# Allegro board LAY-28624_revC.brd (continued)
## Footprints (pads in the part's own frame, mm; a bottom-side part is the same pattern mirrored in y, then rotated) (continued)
BGA_P080_NAND_63
  round 0.35 smd: A1(-3.6,4.4) A2(-2.8,4.4) A9(2.8,4.4) A10(3.6,4.4) B1(-3.6,3.6) B9(2.8,3.6) B10(3.6,3.6) C3(-2,2.8) C4(-1.2,2.8) C5(-0.4,2.8) C6(0.4,2.8) C7(1.2,2.8) C8(2,2.8) D3(-2,2) D4(-1.2,2) D5(-0.4,2) D6(0.4,2) D7(1.2,2) D8(2,2) E3(-2,1.2) E4(-1.2,1.2) E5(-0.4,1.2) E6(0.4,1.2) E7(1.2,1.2) E8(2,1.2) F3(-2,0.4) F4(-1.2,0.4) F5(-0.4,0.4) F6(0.4,0.4) F7(1.2,0.4) F8(2,0.4) G3(-2,-0.4) G4(-1.2,-0.4) G5(-0.4,-0.4) G6(0.4,-0.4) G7(1.2,-0.4) G8(2,-0.4) H3(-2,-1.2) H4(-1.2,-1.2) H5(-0.4,-1.2) H6(0.4,-1.2) H7(1.2,-1.2) H8(2,-1.2) J3(-2,-2) J4(-1.2,-2) J5(-0.4,-2) J6(0.4,-2) J7(1.2,-2) J8(2,-2) K3(-2,-2.8) K4(-1.2,-2.8) K5(-0.4,-2.8) K6(0.4,-2.8) K7(1.2,-2.8) K8(2,-2.8) L1(-3.6,-3.6) L2(-2.8,-3.6) L9(2.8,-3.6) L10(3.6,-3.6) M1(-3.6,-4.4) M2(-2.8,-4.4) M9(2.8,-4.4) M10(3.6,-4.4)
BGA_P100_256
  round 0.4 smd: A1(-7.5,7.5) A2(-6.5,7.5) A3(-5.5,7.5) A4(-4.5,7.5) A5(-3.5,7.5) A6(-2.5,7.5) A7(-1.5,7.5) A8(-0.5,7.5) A9(0.5,7.5) A10(1.5,7.5) A11(2.5,7.5) A12(3.5,7.5) A13(4.5,7.5) A14(5.5,7.5) A15(6.5,7.5) A16(7.5,7.5) B1(-7.5,6.5) B2(-6.5,6.5) B3(-5.5,6.5) B4(-4.5,6.5) B5(-3.5,6.5) B6(-2.5,6.5) B7(-1.5,6.5) B8(-0.5,6.5) B9(0.5,6.5) B10(1.5,6.5) B11(2.5,6.5) B12(3.5,6.5) B13(4.5,6.5) B14(5.5,6.5) B15(6.5,6.5) B16(7.5,6.5) C1(-7.5,5.5) C2(-6.5,5.5) C3(-5.5,5.5) C4(-4.5,5.5) C5(-3.5,5.5) C6(-2.5,5.5) C7(-1.5,5.5) C8(-0.5,5.5) C9(0.5,5.5) C10(1.5,5.5) C11(2.5,5.5) C12(3.5,5.5) C13(4.5,5.5) C14(5.5,5.5) C15(6.5,5.5) C16(7.5,5.5) D1(-7.5,4.5) D2(-6.5,4.5) D3(-5.5,4.5) D4(-4.5,4.5) D5(-3.5,4.5) D6(-2.5,4.5) D7(-1.5,4.5) D8(-0.5,4.5) D9(0.5,4.5) D10(1.5,4.5) D11(2.5,4.5) D12(3.5,4.5) D13(4.5,4.5) D14(5.5,4.5) D15(6.5,4.5) D16(7.5,4.5) E1(-7.5,3.5) E2(-6.5,3.5) E3(-5.5,3.5) E4(-4.5,3.5) E5(-3.5,3.5) E6(-2.5,3.5) E7(-1.5,3.5) E8(-0.5,3.5) E9(0.5,3.5) E10(1.5,3.5) E11(2.5,3.5) E12(3.5,3.5) E13(4.5,3.5) E14(5.5,3.5) E15(6.5,3.5) E16(7.5,3.5) F1(-7.5,2.5) F2(-6.5,2.5) F3(-5.5,2.5) F4(-4.5,2.5) F5(-3.5,2.5) F6(-2.5,2.5) F7(-1.5,2.5) F8(-0.5,2.5) F9(0.5,2.5) F10(1.5,2.5) F11(2.5,2.5) F12(3.5,2.5) F13(4.5,2.5) F14(5.5,2.5) F15(6.5,2.5) F16(7.5,2.5) G1(-7.5,1.5) G2(-6.5,1.5) G3(-5.5,1.5) G4(-4.5,1.5) G5(-3.5,1.5) G6(-2.5,1.5) G7(-1.5,1.5) G8(-0.5,1.5) G9(0.5,1.5) G10(1.5,1.5) G11(2.5,1.5) G12(3.5,1.5) G13(4.5,1.5) G14(5.5,1.5) G15(6.5,1.5) G16(7.5,1.5) H1(-7.5,0.5) H2(-6.5,0.5) H3(-5.5,0.5) H4(-4.5,0.5) H5(-3.5,0.5) H6(-2.5,0.5) H7(-1.5,0.5) H8(-0.5,0.5) H9(0.5,0.5) H10(1.5,0.5) H11(2.5,0.5) H12(3.5,0.5) H13(4.5,0.5) H14(5.5,0.5) H15(6.5,0.5) H16(7.5,0.5) J1(-7.5,-0.5) J2(-6.5,-0.5) J3(-5.5,-0.5) J4(-4.5,-0.5) J5(-3.5,-0.5) J6(-2.5,-0.5) J7(-1.5,-0.5) J8(-0.5,-0.5) J9(0.5,-0.5) J10(1.5,-0.5) J11(2.5,-0.5) J12(3.5,-0.5) J13(4.5,-0.5) J14(5.5,-0.5) J15(6.5,-0.5) J16(7.5,-0.5) K1(-7.5,-1.5) K2(-6.5,-1.5) K3(-5.5,-1.5) K4(-4.5,-1.5) K5(-3.5,-1.5) K6(-2.5,-1.5) K7(-1.5,-1.5) K8(-0.5,-1.5) K9(0.5,-1.5) K10(1.5,-1.5) K11(2.5,-1.5) K12(3.5,-1.5) K13(4.5,-1.5) K14(5.5,-1.5) K15(6.5,-1.5) K16(7.5,-1.5) L1(-7.5,-2.5) L2(-6.5,-2.5) L3(-5.5,-2.5) L4(-4.5,-2.5) L5(-3.5,-2.5) L6(-2.5,-2.5) L7(-1.5,-2.5) L8(-0.5,-2.5) L9(0.5,-2.5) L10(1.5,-2.5) L11(2.5,-2.5) L12(3.5,-2.5) L13(4.5,-2.5) L14(5.5,-2.5) L15(6.5,-2.5) L16(7.5,-2.5) M1(-7.5,-3.5) M2(-6.5,-3.5) M3(-5.5,-3.5) M4(-4.5,-3.5) M5(-3.5,-3.5) M6(-2.5,-3.5) M7(-1.5,-3.5) M8(-0.5,-3.5) M9(0.5,-3.5) M10(1.5,-3.5) M11(2.5,-3.5) M12(3.5,-3.5) M13(4.5,-3.5) M14(5.5,-3.5) M15(6.5,-3.5) M16(7.5,-3.5) N1(-7.5,-4.5) N2(-6.5,-4.5) N3(-5.5,-4.5) N4(-4.5,-4.5) N5(-3.5,-4.5) N6(-2.5,-4.5) N7(-1.5,-4.5) N8(-0.5,-4.5) N9(0.5,-4.5) N10(1.5,-4.5) N11(2.5,-4.5) N12(3.5,-4.5) N13(4.5,-4.5) N14(5.5,-4.5) N15(6.5,-4.5) N16(7.5,-4.5) P1(-7.5,-5.5) P2(-6.5,-5.5) P3(-5.5,-5.5) P4(-4.5,-5.5) P5(-3.5,-5.5) P6(-2.5,-5.5) P7(-1.5,-5.5) P8(-0.5,-5.5) P9(0.5,-5.5) P10(1.5,-5.5) P11(2.5,-5.5) P12(3.5,-5.5) P13(4.5,-5.5) P14(5.5,-5.5) P15(6.5,-5.5) P16(7.5,-5.5) R1(-7.5,-6.5) R2(-6.5,-6.5) R3(-5.5,-6.5) R4(-4.5,-6.5) R5(-3.5,-6.5) R6(-2.5,-6.5) R7(-1.5,-6.5) R8(-0.5,-6.5) R9(0.5,-6.5) R10(1.5,-6.5) R11(2.5,-6.5) R12(3.5,-6.5) R13(4.5,-6.5) R14(5.5,-6.5) R15(6.5,-6.5) R16(7.5,-6.5) T1(-7.5,-7.5) T2(-6.5,-7.5) T3(-5.5,-7.5) T4(-4.5,-7.5) T5(-3.5,-7.5) T6(-2.5,-7.5) T7(-1.5,-7.5) T8(-0.5,-7.5) T9(0.5,-7.5) T10(1.5,-7.5) T11(2.5,-7.5) T12(3.5,-7.5) T13(4.5,-7.5) T14(5.5,-7.5) T15(6.5,-7.5) T16(7.5,-7.5)
BGA_P100_324
  round 0.4 smd: A1(-8.5,8.5) A2(-7.5,8.5) A3(-6.5,8.5) A4(-5.5,8.5) A5(-4.5,8.5) A6(-3.5,8.5) A7(-2.5,8.5) A8(-1.5,8.5) A9(-0.5,8.5) A10(0.5,8.5) A11(1.5,8.5) A12(2.5,8.5) A13(3.5,8.5) A14(4.5,8.5) A15(5.5,8.5) A16(6.5,8.5) A17(7.5,8.5) A18(8.5,8.5) B1(-8.5,7.5) B2(-7.5,7.5) B3(-6.5,7.5) B4(-5.5,7.5) B5(-4.5,7.5) B6(-3.5,7.5) B7(-2.5,7.5) B8(-1.5,7.5) B9(-0.5,7.5) B10(0.5,7.5) B11(1.5,7.5) B12(2.5,7.5) B13(3.5,7.5) B14(4.5,7.5) B15(5.5,7.5) B16(6.5,7.5) B17(7.5,7.5) B18(8.5,7.5) C1(-8.5,6.5) C2(-7.5,6.5) C3(-6.5,6.5) C4(-5.5,6.5) C5(-4.5,6.5) C6(-3.5,6.5) C7(-2.5,6.5) C8(-1.5,6.5) C9(-0.5,6.5) C10(0.5,6.5) C11(1.5,6.5) C12(2.5,6.5) C13(3.5,6.5) C14(4.5,6.5) C15(5.5,6.5) C16(6.5,6.5) C17(7.5,6.5) C18(8.5,6.5) D1(-8.5,5.5) D2(-7.5,5.5) D3(-6.5,5.5) D4(-5.5,5.5) D5(-4.5,5.5) D6(-3.5,5.5) D7(-2.5,5.5) D8(-1.5,5.5) D9(-0.5,5.5) D10(0.5,5.5) D11(1.5,5.5) D12(2.5,5.5) D13(3.5,5.5) D14(4.5,5.5) D15(5.5,5.5) D16(6.5,5.5) D17(7.5,5.5) D18(8.5,5.5) E1(-8.5,4.5) E2(-7.5,4.5) E3(-6.5,4.5) E4(-5.5,4.5) E5(-4.5,4.5) E6(-3.5,4.5) E7(-2.5,4.5) E8(-1.5,4.5) E9(-0.5,4.5) E10(0.5,4.5) E11(1.5,4.5) E12(2.5,4.5) E13(3.5,4.5) E14(4.5,4.5) E15(5.5,4.5) E16(6.5,4.5) E17(7.5,4.5) E18(8.5,4.5) F1(-8.5,3.5) F2(-7.5,3.5) F3(-6.5,3.5) F4(-5.5,3.5) F5(-4.5,3.5) F6(-3.5,3.5) F7(-2.5,3.5) F8(-1.5,3.5) F9(-0.5,3.5) F10(0.5,3.5) F11(1.5,3.5) F12(2.5,3.5) F13(3.5,3.5) F14(4.5,3.5) F15(5.5,3.5) F16(6.5,3.5) F17(7.5,3.5) F18(8.5,3.5) G1(-8.5,2.5) G2(-7.5,2.5) G3(-6.5,2.5) G4(-5.5,2.5) G5(-4.5,2.5) G6(-3.5,2.5) G7(-2.5,2.5) G8(-1.5,2.5) G9(-0.5,2.5) G10(0.5,2.5) G11(1.5,2.5) G12(2.5,2.5) G13(3.5,2.5) G14(4.5,2.5) G15(5.5,2.5) G16(6.5,2.5) G17(7.5,2.5) G18(8.5,2.5) H1(-8.5,1.5) H2(-7.5,1.5) H3(-6.5,1.5) H4(-5.5,1.5) H5(-4.5,1.5) H6(-3.5,1.5) H7(-2.5,1.5) H8(-1.5,1.5) H9(-0.5,1.5) H10(0.5,1.5) H11(1.5,1.5) H12(2.5,1.5) H13(3.5,1.5) H14(4.5,1.5) H15(5.5,1.5) H16(6.5,1.5) H17(7.5,1.5) H18(8.5,1.5) J1(-8.5,0.5) J2(-7.5,0.5) J3(-6.5,0.5) J4(-5.5,0.5) J5(-4.5,0.5) J6(-3.5,0.5) J7(-2.5,0.5) J8(-1.5,0.5) J9(-0.5,0.5) J10(0.5,0.5) J11(1.5,0.5) J12(2.5,0.5) J13(3.5,0.5) J14(4.5,0.5) J15(5.5,0.5) J16(6.5,0.5) J17(7.5,0.5) J18(8.5,0.5) K1(-8.5,-0.5) K2(-7.5,-0.5) K3(-6.5,-0.5) K4(-5.5,-0.5) K5(-4.5,-0.5) K6(-3.5,-0.5) K7(-2.5,-0.5) K8(-1.5,-0.5) K9(-0.5,-0.5) K10(0.5,-0.5) K11(1.5,-0.5) K12(2.5,-0.5) K13(3.5,-0.5) K14(4.5,-0.5) K15(5.5,-0.5) K16(6.5,-0.5) K17(7.5,-0.5) K18(8.5,-0.5) L1(-8.5,-1.5) L2(-7.5,-1.5) L3(-6.5,-1.5) L4(-5.5,-1.5) L5(-4.5,-1.5) L6(-3.5,-1.5) L7(-2.5,-1.5) L8(-1.5,-1.5) L9(-0.5,-1.5) L10(0.5,-1.5) L11(1.5,-1.5) L12(2.5,-1.5) L13(3.5,-1.5) L14(4.5,-1.5) L15(5.5,-1.5) L16(6.5,-1.5) L17(7.5,-1.5) L18(8.5,-1.5) M1(-8.5,-2.5) M2(-7.5,-2.5) M3(-6.5,-2.5) M4(-5.5,-2.5) M5(-4.5,-2.5) M6(-3.5,-2.5) M7(-2.5,-2.5) M8(-1.5,-2.5) M9(-0.5,-2.5) M10(0.5,-2.5) M11(1.5,-2.5) M12(2.5,-2.5) M13(3.5,-2.5) M14(4.5,-2.5) M15(5.5,-2.5) M16(6.5,-2.5) M17(7.5,-2.5) M18(8.5,-2.5) N1(-8.5,-3.5) N2(-7.5,-3.5) N3(-6.5,-3.5) N4(-5.5,-3.5) N5(-4.5,-3.5) N6(-3.5,-3.5) N7(-2.5,-3.5) N8(-1.5,-3.5) N9(-0.5,-3.5) N10(0.5,-3.5) N11(1.5,-3.5) N12(2.5,-3.5) N13(3.5,-3.5) N14(4.5,-3.5) N15(5.5,-3.5) N16(6.5,-3.5) N17(7.5,-3.5) N18(8.5,-3.5) P1(-8.5,-4.5) P2(-7.5,-4.5) P3(-6.5,-4.5) P4(-5.5,-4.5) P5(-4.5,-4.5) P6(-3.5,-4.5) P7(-2.5,-4.5) P8(-1.5,-4.5) P9(-0.5,-4.5) P10(0.5,-4.5) P11(1.5,-4.5) P12(2.5,-4.5) P13(3.5,-4.5) P14(4.5,-4.5) P15(5.5,-4.5) P16(6.5,-4.5) P17(7.5,-4.5) P18(8.5,-4.5) R1(-8.5,-5.5) R2(-7.5,-5.5) R3(-6.5,-5.5) R4(-5.5,-5.5) R5(-4.5,-5.5) R6(-3.5,-5.5) R7(-2.5,-5.5) R8(-1.5,-5.5) R9(-0.5,-5.5) R10(0.5,-5.5) R11(1.5,-5.5) R12(2.5,-5.5) R13(3.5,-5.5) R14(4.5,-5.5) R15(5.5,-5.5) R16(6.5,-5.5) R17(7.5,-5.5) R18(8.5,-5.5) T1(-8.5,-6.5) T2(-7.5,-6.5) T3(-6.5,-6.5) T4(-5.5,-6.5) T5(-4.5,-6.5) T6(-3.5,-6.5) T7(-2.5,-6.5) T8(-1.5,-6.5) T9(-0.5,-6.5) T10(0.5,-6.5) T11(1.5,-6.5) T12(2.5,-6.5) T13(3.5,-6.5) T14(4.5,-6.5) T15(5.5,-6.5) T16(6.5,-6.5) T17(7.5,-6.5) T18(8.5,-6.5) U1(-8.5,-7.5) U2(-7.5,-7.5) U3(-6.5,-7.5) U4(-5.5,-7.5) U5(-4.5,-7.5) U6(-3.5,-7.5) U7(-2.5,-7.5) U8(-1.5,-7.5) U9(-0.5,-7.5) U10(0.5,-7.5) U11(1.5,-7.5) U12(2.5,-7.5) U13(3.5,-7.5) U14(4.5,-7.5) U15(5.5,-7.5) U16(6.5,-7.5) U17(7.5,-7.5) U18(8.5,-7.5) V1(-8.5,-8.5) V2(-7.5,-8.5) V3(-6.5,-8.5) V4(-5.5,-8.5) V5(-4.5,-8.5) V6(-3.5,-8.5) V7(-2.5,-8.5) V8(-1.5,-8.5) V9(-0.5,-8.5) V10(0.5,-8.5) V11(1.5,-8.5) V12(2.5,-8.5) V13(3.5,-8.5) V14(4.5,-8.5) V15(5.5,-8.5) V16(6.5,-8.5) V17(7.5,-8.5) V18(8.5,-8.5)
CAPE_B6D3
  rect 3.5x1.6 smd: 1(-2.8,0) 2(2.8,0)
CAPE_B8
  rect 4.15x1.9 smd: 1(-3.475,0) 2(3.475,0)
CON_ATX_20PIN
  rect 1.9x1.9 hole 1.4: 1(-18.9,2.75)
  round 1.9 hole 1.4: 2(-14.7,2.75) 3(-10.5,2.75) 4(-6.3,2.75) 5(-2.1,2.75) 6(2.1,2.75) 7(6.3,2.75) 8(10.5,2.75) 9(14.7,2.75) 10(18.9,2.75) 11(-18.9,-2.75) 12(-14.7,-2.75) 13(-10.5,-2.75) 14(-6.3,-2.75) 15(-2.1,-2.75) 16(2.1,-2.75) 17(6.3,-2.75) 18(10.5,-2.75) 19(14.7,-2.75) 20(18.9,-2.75)
CON_BAT_WBA3B2
  round 1.5 hole 0.9: (-5,1.735) 2(0,-1.735)
  rect 1.5x1.5 hole 0.9: 1(5,1.735)
CON_DDR3_DIMM
  round 2.45 hole 2.45 unplated: (-57,0) (0,0) (81,0)
  round 1 hole 0.7: 1(-49.5,-0.95) 2(-48.5,-2.85) 3(-47.5,-0.95) 4(-46.5,-2.85) 5(-45.5,-0.95) 6(-44.5,-2.85) 7(-43.5,-0.95) 8(-42.5,-2.85) 9(-41.5,-0.95) 10(-40.5,-2.85) 11(-39.5,-0.95) 12(-38.5,-2.85) 13(-37.5,-0.95) 14(-36.5,-2.85) 15(-35.5,-0.95) 16(-34.5,-2.85) 17(-33.5,-0.95) 18(-32.5,-2.85) 19(-31.5,-0.95) 20(-30.5,-2.85) 21(-29.5,-0.95) 22(-28.5,-2.85) 23(-27.5,-0.95) 24(-26.5,-2.85) 25(-25.5,-0.95) 26(-24.5,-2.85) 27(-23.5,-0.95) 28(-22.5,-2.85) 29(-21.5,-0.95) 30(-20.5,-2.85) 31(-19.5,-0.95) 32(-18.5,-2.85) 33(-17.5,-0.95) 34(-16.5,-2.85) 35(-15.5,-0.95) 36(-14.5,-2.85) 37(-13.5,-0.95) 38(-12.5,-2.85) 39(-11.5,-0.95) 40(-10.5,-2.85) 41(-9.5,-0.95) 42(-8.5,-2.85) 43(-7.5,-0.95) 44(-6.5,-2.85) 45(-5.5,-0.95) 46(-4.5,-2.85) 47(-3.5,-0.95) 48(-2.5,-2.85) 49(2.5,-0.95) 50(3.5,-2.85) 51(4.5,-0.95) 52(5.5,-2.85) 53(6.5,-0.95) 54(7.5,-2.85) 55(8.5,-0.95) 56(9.5,-2.85) 57(10.5,-0.95) 58(11.5,-2.85) 59(12.5,-0.95) 60(13.5,-2.85) 61(14.5,-0.95) 62(15.5,-2.85) 63(16.5,-0.95) 64(17.5,-2.85) 65(18.5,-0.95) 66(19.5,-2.85) 67(20.5,-0.95) 68(21.5,-2.85) 69(22.5,-0.95) 70(23.5,-2.85) 71(24.5,-0.95) 72(25.5,-2.85) 73(26.5,-0.95) 74(27.5,-2.85) 75(28.5,-0.95) 76(29.5,-2.85) 77(30.5,-0.95) 78(31.5,-2.85) 79(32.5,-0.95) 80(33.5,-2.85) 81(34.5,-0.95) 82(35.5,-2.85) 83(36.5,-0.95) 84(37.5,-2.85) 85(38.5,-0.95) 86(39.5,-2.85) 87(40.5,-0.95) 88(41.5,-2.85) 89(42.5,-0.95) 90(43.5,-2.85) 91(44.5,-0.95) 92(45.5,-2.85) 93(46.5,-0.95) 94(47.5,-2.85) 95(48.5,-0.95) 96(49.5,-2.85) 97(50.5,-0.95) 98(51.5,-2.85) 99(52.5,-0.95) 100(53.5,-2.85) 101(54.5,-0.95) 102(55.5,-2.85) 103(56.5,-0.95) 104(57.5,-2.85) 105(58.5,-0.95) 106(59.5,-2.85) 107(60.5,-0.95) 108(61.5,-2.85) 109(62.5,-0.95) 110(63.5,-2.85) 111(64.5,-0.95) 112(65.5,-2.85) 113(66.5,-0.95) 114(67.5,-2.85) 115(68.5,-0.95) 116(69.5,-2.85) 117(70.5,-0.95) 118(71.5,-2.85) 119(72.5,-0.95) 120(73.5,-2.85) 121(-49.5,2.85) 122(-48.5,0.95) 123(-47.5,2.85) 124(-46.5,0.95) 125(-45.5,2.85) 126(-44.5,0.95) 127(-43.5,2.85) 128(-42.5,0.95) 129(-41.5,2.85) 130(-40.5,0.95) 131(-39.5,2.85) 132(-38.5,0.95) 133(-37.5,2.85) 134(-36.5,0.95) 135(-35.5,2.85) 136(-34.5,0.95) 137(-33.5,2.85) 138(-32.5,0.95) 139(-31.5,2.85) 140(-30.5,0.95) 141(-29.5,2.85) 142(-28.5,0.95) 143(-27.5,2.85) 144(-26.5,0.95) 145(-25.5,2.85) 146(-24.5,0.95) 147(-23.5,2.85) 148(-22.5,0.95) 149(-21.5,2.85) 150(-20.5,0.95) 151(-19.5,2.85) 152(-18.5,0.95) 153(-17.5,2.85) 154(-16.5,0.95) 155(-15.5,2.85) 156(-14.5,0.95) 157(-13.5,2.85) 158(-12.5,0.95) 159(-11.5,2.85) 160(-10.5,0.95) 161(-9.5,2.85) 162(-8.5,0.95) 163(-7.5,2.85) 164(-6.5,0.95) 165(-5.5,2.85) 166(-4.5,0.95) 167(-3.5,2.85) 168(-2.5,0.95) 169(2.5,2.85) 170(3.5,0.95) 171(4.5,2.85) 172(5.5,0.95) 173(6.5,2.85) 174(7.5,0.95) 175(8.5,2.85) 176(9.5,0.95) 177(10.5,2.85) 178(11.5,0.95) 179(12.5,2.85) 180(13.5,0.95) 181(14.5,2.85) 182(15.5,0.95) 183(16.5,2.85) 184(17.5,0.95) 185(18.5,2.85) 186(19.5,0.95) 187(20.5,2.85) 188(21.5,0.95) 189(22.5,2.85) 190(23.5,0.95) 191(24.5,2.85) 192(25.5,0.95) 193(26.5,2.85) 194(27.5,0.95) 195(28.5,2.85) 196(29.5,0.95) 197(30.5,2.85) 198(31.5,0.95) 199(32.5,2.85) 200(33.5,0.95) 201(34.5,2.85) 202(35.5,0.95) 203(36.5,2.85) 204(37.5,0.95) 205(38.5,2.85) 206(39.5,0.95) 207(40.5,2.85) 208(41.5,0.95) 209(42.5,2.85) 210(43.5,0.95) 211(44.5,2.85) 212(45.5,0.95) 213(46.5,2.85) 214(47.5,0.95) 215(48.5,2.85) 216(49.5,0.95) 217(50.5,2.85) 218(51.5,0.95) 219(52.5,2.85) 220(53.5,0.95) 221(54.5,2.85) 222(55.5,0.95) 223(56.5,2.85) 224(57.5,0.95) 225(58.5,2.85) 226(59.5,0.95) 227(60.5,2.85) 228(61.5,0.95) 229(62.5,2.85) 230(63.5,0.95) 231(64.5,2.85) 232(65.5,0.95) 233(66.5,2.85) 234(67.5,0.95) 235(68.5,2.85) 236(69.5,0.95) 237(70.5,2.85) 238(71.5,0.95) 239(72.5,2.85) 240(73.5,0.95)
CON_MEC6_120
  round 1.55 hole 1.55 unplated: (-1.5,7.535) (0,-7.535)
  rect 1.8x0.4 smd: 1(3.85,6.033) 2(-3.85,6.033) 3(3.85,5.398) 4(-3.85,5.398) 5(3.85,4.763) 6(-3.85,4.763) 7(3.85,4.128) 8(-3.85,4.128) 9(3.85,3.493) 10(-3.85,3.493) 11(3.85,2.858) 12(-3.85,2.858) 13(3.85,2.223) 14(-3.85,2.223) 15(3.85,1.588) 16(-3.85,1.588) 17(3.85,0.953) 18(-3.85,0.953) 19(3.85,0.318) 20(-3.85,0.318) 21(3.85,-0.317) 22(-3.85,-0.317) 23(3.85,-0.952) 24(-3.85,-0.952) 25(3.85,-1.587) 26(-3.85,-1.587) 27(3.85,-2.222) 28(-3.85,-2.222) 29(3.85,-2.857) 30(-3.85,-2.857) 31(3.85,-3.492) 32(-3.85,-3.492) 33(3.85,-4.127) 34(-3.85,-4.127) 35(3.85,-4.762) 36(-3.85,-4.762) 37(3.85,-5.397) 38(-3.85,-5.397) 39(3.85,-6.032) 40(-3.85,-6.032)
CON_MINIPCIE
  round 1.1 hole 1.1 unplated: (-12.5,0)
  round 1.6 hole 1.6 unplated: (12.5,0)
  rect 0.6x2 smd: 1(11.8,4.1) 2(11.4,-4.1) 3(11,4.1) 4(10.6,-4.1) 5(10.2,4.1) 6(9.8,-4.1) 7(9.4,4.1) 8(9,-4.1) 9(8.6,4.1) 10(8.2,-4.1) 11(7.8,4.1) 12(7.4,-4.1) 13(7,4.1) 14(6.6,-4.1) 15(6.2,4.1) 16(5.8,-4.1) 17(2.2,4.1) 18(1.8,-4.1) 19(1.4,4.1) 20(1,-4.1) 21(0.6,4.1) 22(0.2,-4.1) 23(-0.2,4.1) 24(-0.6,-4.1) 25(-1,4.1) 26(-1.4,-4.1) 27(-1.8,4.1) 28(-2.2,-4.1) 29(-2.6,4.1) 30(-3,-4.1) 31(-3.4,4.1) 32(-3.8,-4.1) 33(-4.2,4.1) 34(-4.6,-4.1) 35(-5,4.1) 36(-5.4,-4.1) 37(-5.8,4.1) 38(-6.2,-4.1) 39(-6.6,4.1) 40(-7,-4.1) 41(-7.4,4.1) 42(-7.8,-4.1) 43(-8.2,4.1) 44(-8.6,-4.1) 45(-9,4.1) 46(-9.4,-4.1) 47(-9.8,4.1) 48(-10.2,-4.1) 49(-10.6,4.1) 50(-11,-4.1) 51(-11.4,4.1) 52(-11.8,-4.1)
  rect 2.3x3.2 smd: 53(14.65,3.5) 54(-14.65,3.5)
CON_PEX1
  round 2.35 hole 2.35 unplated: (0,0) (9.15,0)
  rect 1.1x1.1 hole 0.7: A1(-11.65,1.25)
  round 1.1 hole 0.7: A2(-10.65,3.25) A3(-9.65,1.25) A4(-8.65,3.25) A5(-7.65,1.25) A6(-6.65,3.25) A7(-5.65,1.25) A8(-4.65,3.25) A9(-3.65,1.25) A10(-2.65,3.25) A11(-1.65,1.25) A12(1.35,3.25) A13(2.35,1.25) A14(3.35,3.25) A15(4.35,1.25) A16(5.35,3.25) A17(6.35,1.25) A18(7.35,3.25) B1(-11.65,-1.25) B2(-10.65,-3.25) B3(-9.65,-1.25) B4(-8.65,-3.25) B5(-7.65,-1.25) B6(-6.65,-3.25) B7(-5.65,-1.25) B8(-4.65,-3.25) B9(-3.65,-1.25) B10(-2.65,-3.25) B11(-1.65,-1.25) B12(1.35,-3.25) B13(2.35,-1.25) B14(3.35,-3.25) B15(4.35,-1.25) B16(5.35,-3.25) B17(6.35,-1.25) B18(7.35,-3.25)
CON_RJ45_2X1
  round 3.2 hole 3.2 unplated: (-5.715,10.8) (5.715,10.8)
  round 2.2 hole 1.6: 17(-8.505,26.29) 18(8.505,22.23) 19(-7.745,19.94) 20(7.745,16.64) 21(-8.505,6.23) 22(8.505,6.23)
  round 1.4 hole 0.9: A1(4.445,26.31) A2(3.175,23.77) A3(1.905,26.31) A4(0.635,23.77) A5(-0.635,26.31) A6(-1.905,23.77) A7(-3.175,26.31) A8(-4.445,23.77) B1(-4.445,17.15) B2(-3.175,19.69) B3(-1.905,17.15) B4(-0.635,19.69) B5(0.635,17.15) B6(1.905,19.69) B7(3.175,17.15) B8(4.445,19.69)
CON_RJ45_2X1_LED
  round 3.2 hole 3.2 unplated: (-6.35,5.46) (6.35,5.46)
  round 2.2 hole 1.6: 25(-8.13,12.57) 26(8.13,12.57) 27(-8.13,20.95) 28(8.13,20.95)
  round 1.4 hole 0.9: A1(4.445,22.48) A2(3.175,19.94) A3(1.905,22.48) A4(0.635,19.94) A5(-0.635,22.48) A6(-1.905,19.94) A7(-3.175,22.48) A8(-4.445,19.94) B1(-4.445,13.71) B2(-3.175,16.25) B3(-1.905,13.71) B4(-0.635,16.25) B5(0.635,13.71) B6(1.905,16.25) B7(3.175,13.71) B8(4.445,16.25)
  round 1.6 hole 1.1: A9(-6.86,26.41) A10(-4.32,26.41) A11(4.32,26.41) A12(6.86,26.41) B9(-6.86,9.65) B10(-4.32,9.65) B11(4.32,9.65) B12(6.86,9.65)
CON_RJ45_XG_1X1_LED
  round 3.25 hole 3.25 unplated: (-4.825,13.21) (4.825,13.21)
  round 1.3 hole 0.9: 1(5.1,19.81) 2(3.06,19.81) 3(1.02,19.81) 4(-1.02,19.81) 5(-3.06,19.81) 6(-5.1,19.81) 7(6.12,22.35) 8(4.08,22.35) 9(2.04,22.35) 10(-2.04,22.35) 11(-4.08,22.35) 12(-6.12,22.35) 13(5.1,24.89) 14(-3.06,24.89) 15(-5.1,24.89)
  round 1.65 hole 1.15: 16(7.52,9.4) 17(7.52,6.86) 18(-7.52,9.4) 19(-7.52,6.86)
  round 2.2 hole 1.6: 20(-8.79,13.21) 21(8.79,13.21)
CON_SD
  round 1.5 hole 1.5 unplated: (-12.1,5.5) (12.1,5.5)
  rect 0.8x2 smd: 1(-6.88,30) 2(-4.38,30) 3(-1.05,30) 4(0.62,30) 5(3.12,30) 6(5.62,30) 7(8.05,30) 8(9.75,30) 9(-9.38,30) 10(-2.71,30)
  rect 0.7x2 smd: 11(13.24,30)
  rect 1.8x2.4 smd: 12(-14.1,8.8)
  rect 1.7x2.4 smd: 13(13.25,7.6)
CON_SW_60X60_2P2_34
  round 1.5 hole 1: 1(-2.25,2.45) 2(2.25,2.45)
  round 1.8 hole 1.3: 3(-3.5,4.95) 4(3.5,4.95)
CON_SWITCH_X8
  rect 1.27x0.76 smd: 1(-3.81,4.445) 2(-3.81,3.175) 3(-3.81,1.905) 4(-3.81,0.635) 5(-3.81,-0.635) 6(-3.81,-1.905) 7(-3.81,-3.175) 8(-3.81,-4.445) 9(3.81,-4.445) 10(3.81,-3.175) 11(3.81,-1.905) 12(3.81,-0.635) 13(3.81,0.635) 14(3.81,1.905) 15(3.81,3.175) 16(3.81,4.445)
CON_USB_A_2
  round 1.4 hole 0.9: 1(-3.5,15.61) 2(-1,15.61) 3(1,15.61) 4(3.5,15.61) 5(-3.5,12.99) 6(-1,12.99) 7(1,12.99) 8(3.5,12.99)
  round 3.3 hole 2.3: 9(-6.57,10.28) 10(6.57,10.28) 11(-6.57,15.96) 12(6.57,15.96)
CON_WAFER_P254_S_1X3
  round 1.5 hole 1: 1(-2.54,0) 2(0,0) 3(2.54,0)
CRY_32X25_4
  rect 1.4x1.2 smd: 1(-1.1,-0.85) 2(1.1,-0.85) 3(1.1,0.85) 4(-1.1,0.85)
CRY_69X14_4
  rect 1.2x0.6 smd: 1(-3.15,-0.45) 2(3.15,-0.45) 3(3.15,0.45) 4(-3.15,0.45)
DFN_P050_D040_B300_10_E230X150
  custom 0.07x0.07 smd: 1(-1.5,1) 2(-1.5,0.5) 3(-1.5,0) 4(-1.5,-0.5) 5(-1.5,-1) 6(1.5,-1) 7(1.5,-0.5) 8(1.5,0) 9(1.5,0.5) 10(1.5,1)
  rect 1.5x2.3 smd: 11(0,0)
DFN_P050_D040_B300_10_E240X165
  custom 0.07x0.07 smd: 1(-1.5,1) 2(-1.5,0.5) 3(-1.5,0) 4(-1.5,-0.5) 5(-1.5,-1) 6(1.5,-1) 7(1.5,-0.5) 8(1.5,0) 9(1.5,0.5) 10(1.5,1)
  custom 0.412x0.412 smd: 11(0,0)
FIDUCIAL
  round 1 smd: 1(0,0)
HDR_P254_HTST_2X8
  rect 5.08x1.27 smd: 1(-3.43,0) 2(3.43,0) 3(-3.43,-2.54) 4(3.43,-2.54) 5(-3.43,-5.08) 6(3.43,-5.08) 7(-3.43,-7.62) 8(3.43,-7.62) 9(-3.43,-10.16) 10(3.43,-10.16) 11(-3.43,-12.7) 12(3.43,-12.7) 13(-3.43,-15.24) 14(3.43,-15.24) 15(-3.43,-17.78) 16(3.43,-17.78)
HDR_P254_M_T_1X3
  rect 1.5x1.5 hole 1: 1(0,0)
  round 1.5 hole 1: 2(0,-2.54) 3(0,-5.08)
HDR_P254_M_T_1X7
  rect 1.5x1.5 hole 1: 1(0,0)
  round 1.5 hole 1: 2(0,-2.54) 3(0,-5.08) 4(0,-7.62) 5(0,-10.16) 6(0,-12.7) 7(0,-15.24)
HDR_P254_M_T_2X5
  rect 1.5x1.5 hole 1: 1(-1.27,0)
  round 1.5 hole 1: 2(1.27,0) 3(-1.27,-2.54) 4(1.27,-2.54) 5(-1.27,-5.08) 6(1.27,-5.08) 7(-1.27,-7.62) 8(1.27,-7.62) 9(-1.27,-10.16) 10(1.27,-10.16)
IND_45X40
  custom 0.412x0.412 smd: 1(0,1.675) 2(0,-1.675)
IND_CM_2012
  rect 0.9x0.4 smd: 1(-0.85,-0.35) 2(0.85,-0.35) 3(0.85,0.35) 4(-0.85,0.35)
IND_IHLP_2525
  rect 1.83x3.43 smd: 1(-2.77,0) 2(2.77,0)
IND_IHLP_4040
  rect 3.5x4.95 smd: 1(-4.75,0) 2(4.75,0)
IND_SWPA2520
  rect 0.85x2 smd: 1(-0.825,0) 2(0.825,0)
JMP_P254_T_1X1
  round 1.5 hole 1: 1(0,0)
JMP_P254_T_1X2
  round 1.5 hole 1: 1(0,0) 2(0,-2.54)
JMP_P254_T_1X3
  round 1.5 hole 1: 1(0,0) 2(0,-2.54) 3(0,-5.08)
LED_0603
  rect 0.9x0.9 smd: 1(-0.8,0) 2(0.8,0)
LED_PM_1S
  rect 1.5x3.5 smd: 1(1.27,5.25) 2(-1.27,5.25)
MAG_GST5009
  rect 0.6x1.35 smd: 1(-5.5,-4.675) 2(-4.5,-4.675) 3(-3.5,-4.675) 4(-2.5,-4.675) 5(-1.5,-4.675) 6(-0.5,-4.675) 7(0.5,-4.675) 8(1.5,-4.675) 9(2.5,-4.675) 10(3.5,-4.675) 11(4.5,-4.675) 12(5.5,-4.675) 13(5.5,4.675) 14(4.5,4.675) 15(3.5,4.675) 16(2.5,4.675) 17(1.5,4.675) 18(0.5,4.675) 19(-0.5,4.675) 20(-1.5,4.675) 21(-2.5,4.675) 22(-3.5,4.675) 23(-4.5,4.675) 24(-5.5,4.675)
MH_580S340P
  rect 5.8x5.8 hole 3.4: 1(0,0)
MH_900C400N_M
  round 4 hole 4 unplated: (0,0)
  round 1 hole 0.5: 1(0,3) 2(-2.121,2.121) 3(-3,0) 4(-2.121,-2.121) 5(0,-3) 6(2.121,-2.121) 7(3,0) 8(2.121,2.121)
MSOP_8
  rect 1.5x0.35 smd: 1(-2.2,0.975) 2(-2.2,0.325) 3(-2.2,-0.325) 4(-2.2,-0.975) 5(2.2,-0.975) 6(2.2,-0.325) 7(2.2,0.325) 8(2.2,0.975)
MSOP_8_E170
  rect 1.5x0.35 smd: 1(-2.2,0.975) 2(-2.2,0.325) 3(-2.2,-0.325) 4(-2.2,-0.975) 5(2.2,-0.975) 6(2.2,-0.325) 7(2.2,0.325) 8(2.2,0.975)
  rect 1.7x1.7 smd: 9(0,0)
MSOP_10
  rect 1.5x0.28 smd: 1(-2.2,1) 2(-2.2,0.5) 3(-2.2,0) 4(-2.2,-0.5) 5(-2.2,-1) 6(2.2,-1) 7(2.2,-0.5) 8(2.2,0) 9(2.2,0.5) 10(2.2,1)
NFM21
  rect 0.8x1.4 smd: 1(-1,0) 2(1,0)
  rect 0.7x0.7 smd: 3(0,0.625) 4(0,-0.625)
OSC_7X5_4
  rect 1.8x2 smd: 1(-2.54,-2.1) 2(2.54,-2.1) 3(2.54,2.1) 4(-2.54,2.1)
OSC_32X25_4
  rect 1.4x1.2 smd: 1(-1.1,-0.85) 2(1.1,-0.85) 3(1.1,0.85) 4(-1.1,0.85)
QFN_P040_D040_B260X180_16
  custom 0.05x0.05 smd: 1(-0.9,0.6) 2(-0.9,0.2) 3(-0.9,-0.2) 4(-0.9,-0.6) 5(-0.6,-1.3) 6(-0.2,-1.3) 7(0.2,-1.3) 8(0.6,-1.3) 9(0.9,-0.6) 10(0.9,-0.2) 11(0.9,0.2) 12(0.9,0.6) 13(0.6,1.3) 14(0.2,1.3) 15(-0.2,1.3) 16(-0.6,1.3)
QFN_P040_D040_B500_40_E370
  custom 0.05x0.05 smd: 1(-2.5,1.8) 2(-2.5,1.4) 3(-2.5,1) 4(-2.5,0.6) 5(-2.5,0.2) 6(-2.5,-0.2) 7(-2.5,-0.6) 8(-2.5,-1) 9(-2.5,-1.4) 10(-2.5,-1.8) 11(-1.8,-2.5) 12(-1.4,-2.5) 13(-1,-2.5) 14(-0.6,-2.5) 15(-0.2,-2.5) 16(0.2,-2.5) 17(0.6,-2.5) 18(1,-2.5) 19(1.4,-2.5) 20(1.8,-2.5) 21(2.5,-1.8) 22(2.5,-1.4) 23(2.5,-1) 24(2.5,-0.6) 25(2.5,-0.2) 26(2.5,0.2) 27(2.5,0.6) 28(2.5,1) 29(2.5,1.4) 30(2.5,1.8) 31(1.8,2.5) 32(1.4,2.5) 33(1,2.5) 34(0.6,2.5) 35(0.2,2.5) 36(-0.2,2.5) 37(-0.6,2.5) 38(-1,2.5) 39(-1.4,2.5) 40(-1.8,2.5)
  rect 3.7x3.7 smd: 41(0,0)
QFN_P040_D040_B600_48_E440
  custom 0.05x0.05 smd: 1(-3,2.2) 2(-3,1.8) 3(-3,1.4) 4(-3,1) 5(-3,0.6) 6(-3,0.2) 7(-3,-0.2) 8(-3,-0.6) 9(-3,-1) 10(-3,-1.4) 11(-3,-1.8) 12(-3,-2.2) 13(-2.2,-3) 14(-1.8,-3) 15(-1.4,-3) 16(-1,-3) 17(-0.6,-3) 18(-0.2,-3) 19(0.2,-3) 20(0.6,-3) 21(1,-3) 22(1.4,-3) 23(1.8,-3) 24(2.2,-3) 25(3,-2.2) 26(3,-1.8) 27(3,-1.4) 28(3,-1) 29(3,-0.6) 30(3,-0.2) 31(3,0.2) 32(3,0.6) 33(3,1) 34(3,1.4) 35(3,1.8) 36(3,2.2) 37(2.2,3) 38(1.8,3) 39(1.4,3) 40(1,3) 41(0.6,3) 42(0.2,3) 43(-0.2,3) 44(-0.6,3) 45(-1,3) 46(-1.4,3) 47(-1.8,3) 48(-2.2,3)
  rect 4.4x4.4 smd: 49(0,0)
QFN_P050_D040_B450X250_20_E3X1
  custom 0.07x0.07 smd: 1(-0.25,2.25) 2(-1.25,1.75) 3(-1.25,1.25) 4(-1.25,0.75) 5(-1.25,0.25) 6(-1.25,-0.25) 7(-1.25,-0.75) 8(-1.25,-1.25) 9(-1.25,-1.75) 10(-0.25,-2.25) 11(0.25,-2.25) 12(1.25,-1.75) 13(1.25,-1.25) 14(1.25,-0.75) 15(1.25,-0.25) 16(1.25,0.25) 17(1.25,0.75) 18(1.25,1.25) 19(1.25,1.75) 20(0.25,2.25)
  rect 1x3 smd: 21(0,0)
QFN_SUPIRBUCK_4X5
  custom 0.07x0.07 smd: 1(-1.5,-2.5) 2(-1,-2.5) 3(-0.5,-2.5) 4(0,-2.5) 5(0.5,-2.5) 6(1,-2.5) 7(1.5,-2.5) 8(2,-1.65) 9(2,-1.15) 10(2,-0.65) 14(-2,-0.65) 15(-2,-1.15) 16(-2,-1.65)
  rect 0.92x2.07 smd: 11(1.9,1.205)
  rect 1.74x2.94 smd: 12(0.29,1.39)
  rect 1.49x2.07 smd: 13(-1.615,1.205)
  custom 0.33x0.33 smd: 17(0,-1.15)
RES_WSL2726
  rect 2.44x5.6 smd: 1(-2.48,1.14) 4(2.48,1.14)
  rect 2.44x0.89 smd: 2(-2.48,-2.995) 3(2.48,-2.995)
SC70_5
  rect 0.4x0.8 smd: 1(-0.65,-0.95) 2(0,-0.95) 3(0.65,-0.95) 4(0.65,0.95) 5(-0.65,0.95)
SO_8
  rect 1.7x0.6 smd: 1(-2.65,1.905) 2(-2.65,0.635) 3(-2.65,-0.635) 4(-2.65,-1.905) 5(2.65,-1.905) 6(2.65,-0.635) 7(2.65,0.635) 8(2.65,1.905)
SO_8_FL
  rect 0.75x1 smd: 1(-1.905,-2.795) 2(-0.635,-2.795) 3(0.635,-2.795) 4(1.905,-2.795)
  custom 1.132x1.132 smd: 5(0,0)
SO_16
  rect 1.7x0.6 smd: 1(-2.65,4.445) 2(-2.65,3.175) 3(-2.65,1.905) 4(-2.65,0.635) 5(-2.65,-0.635) 6(-2.65,-1.905) 7(-2.65,-3.175) 8(-2.65,-4.445) 9(2.65,-4.445) 10(2.65,-3.175) 11(2.65,-1.905) 12(2.65,-0.635) 13(2.65,0.635) 14(2.65,1.905) 15(2.65,3.175) 16(2.65,4.445)
SO_16L
  rect 1.7x0.6 smd: 1(-4.8,4.445) 2(-4.8,3.175) 3(-4.8,1.905) 4(-4.8,0.635) 5(-4.8,-0.635) 6(-4.8,-1.905) 7(-4.8,-3.175) 8(-4.8,-4.445) 9(4.8,-4.445) 10(4.8,-3.175) 11(4.8,-1.905) 12(4.8,-0.635) 13(4.8,0.635) 14(4.8,1.905) 15(4.8,3.175) 16(4.8,4.445)
SOD123
  rect 1.2x0.7 smd: 1(-1.85,0) 2(1.85,0)
SOD323
  rect 1.35x0.65 smd: 1(-1.1,0) 2(1.1,0)
SOD523
  rect 0.8x0.6 smd: 1(-0.85,0) 2(0.85,0)
SOT23
  rect 0.8x1 smd: 1(-0.95,-1.15) 2(0.95,-1.15) 3(0,1.15)
SOT23_6
  rect 0.7x1 smd: 1(-0.95,-1.3) 2(0,-1.3) 3(0.95,-1.3) 4(0.95,1.3) 5(0,1.3) 6(-0.95,1.3)
SOT143
  rect 1.2x1 smd: 1(-0.75,-1.15)
  rect 0.8x1 smd: 2(0.95,-1.15) 3(0.95,1.15) 4(-0.95,1.15)
TP
  round 0.8 smd: 1(0,0)
TSOP1_56
  rect 1.6x0.28 smd: 1(-9.7,6.75) 2(-9.7,6.25) 3(-9.7,5.75) 4(-9.7,5.25) 5(-9.7,4.75) 6(-9.7,4.25) 7(-9.7,3.75) 8(-9.7,3.25) 9(-9.7,2.75) 10(-9.7,2.25) 11(-9.7,1.75) 12(-9.7,1.25) 13(-9.7,0.75) 14(-9.7,0.25) 15(-9.7,-0.25) 16(-9.7,-0.75) 17(-9.7,-1.25) 18(-9.7,-1.75) 19(-9.7,-2.25) 20(-9.7,-2.75) 21(-9.7,-3.25) 22(-9.7,-3.75) 23(-9.7,-4.25) 24(-9.7,-4.75) 25(-9.7,-5.25) 26(-9.7,-5.75) 27(-9.7,-6.25) 28(-9.7,-6.75) 29(9.7,-6.75) 30(9.7,-6.25) 31(9.7,-5.75) 32(9.7,-5.25) 33(9.7,-4.75) 34(9.7,-4.25) 35(9.7,-3.75) 36(9.7,-3.25) 37(9.7,-2.75) 38(9.7,-2.25) 39(9.7,-1.75) 40(9.7,-1.25) 41(9.7,-0.75) 42(9.7,-0.25) 43(9.7,0.25) 44(9.7,0.75) 45(9.7,1.25) 46(9.7,1.75) 47(9.7,2.25) 48(9.7,2.75) 49(9.7,3.25) 50(9.7,3.75) 51(9.7,4.25) 52(9.7,4.75) 53(9.7,5.25) 54(9.7,5.75) 55(9.7,6.25) 56(9.7,6.75)
TSSOP_16
  rect 1.65x0.35 smd: 1(-2.875,2.275) 2(-2.875,1.625) 3(-2.875,0.975) 4(-2.875,0.325) 5(-2.875,-0.325) 6(-2.875,-0.975) 7(-2.875,-1.625) 8(-2.875,-2.275) 9(2.875,-2.275) 10(2.875,-1.625) 11(2.875,-0.975) 12(2.875,-0.325) 13(2.875,0.325) 14(2.875,0.975) 15(2.875,1.625) 16(2.875,2.275)
TSSOP_20
  rect 1.65x0.35 smd: 1(-2.875,2.925) 2(-2.875,2.275) 3(-2.875,1.625) 4(-2.875,0.975) 5(-2.875,0.325) 6(-2.875,-0.325) 7(-2.875,-0.975) 8(-2.875,-1.625) 9(-2.875,-2.275) 10(-2.875,-2.925) 11(2.875,-2.925) 12(2.875,-2.275) 13(2.875,-1.625) 14(2.875,-0.975) 15(2.875,-0.325) 16(2.875,0.325) 17(2.875,0.975) 18(2.875,1.625) 19(2.875,2.275) 20(2.875,2.925)
TSSOP_48W
  rect 1.65x0.28 smd: 1(-3.725,5.75) 2(-3.725,5.25) 3(-3.725,4.75) 4(-3.725,4.25) 5(-3.725,3.75) 6(-3.725,3.25) 7(-3.725,2.75) 8(-3.725,2.25) 9(-3.725,1.75) 10(-3.725,1.25) 11(-3.725,0.75) 12(-3.725,0.25) 13(-3.725,-0.25) 14(-3.725,-0.75) 15(-3.725,-1.25) 16(-3.725,-1.75) 17(-3.725,-2.25) 18(-3.725,-2.75) 19(-3.725,-3.25) 20(-3.725,-3.75) 21(-3.725,-4.25) 22(-3.725,-4.75) 23(-3.725,-5.25) 24(-3.725,-5.75) 25(3.725,-5.75) 26(3.725,-5.25) 27(3.725,-4.75) 28(3.725,-4.25) 29(3.725,-3.75) 30(3.725,-3.25) 31(3.725,-2.75) 32(3.725,-2.25) 33(3.725,-1.75) 34(3.725,-1.25) 35(3.725,-0.75) 36(3.725,-0.25) 37(3.725,0.25) 38(3.725,0.75) 39(3.725,1.25) 40(3.725,1.75) 41(3.725,2.25) 42(3.725,2.75) 43(3.725,3.25) 44(3.725,3.75) 45(3.725,4.25) 46(3.725,4.75) 47(3.725,5.25) 48(3.725,5.75)
TVS_LLP75_6L
  rect 0.55x0.25 smd: 1(-0.775,0.5) 3(-0.775,-0.5) 4(0.775,-0.5) 5(0.775,0) 6(0.775,0.5)
  custom 0.25x0.25 smd: 2(0,0)
TVS_SLP2710P8
  rect 0.2x0.675 smd: 1(-1.1,-0.438) 2(-0.6,-0.438) 3(0.6,-0.438) 4(1.1,-0.438) 5(1.1,0.438) 6(0.6,0.438) 7(-0.6,0.438) 8(-1.1,0.438)
  rect 0.4x1.55 smd: 9(0,0)
U8
  rect 1x0.28 smd: 1(-1.45,0.75) 2(-1.45,0.25) 3(-1.45,-0.25) 4(-1.45,-0.75) 5(1.45,-0.75) 6(1.45,-0.25) 7(1.45,0.25) 8(1.45,0.75)
U8_FL
  rect 0.4x0.76 smd: 1(-0.975,-1.52) 2(-0.325,-1.52) 3(0.325,-1.52) 4(0.975,-1.52)
  custom 0.588x0.588 smd: 5(0,0)
unnamed
  round 3.71 hole 3.71 unplated: (-24.13,24.13) (-24.13,-24.13) (24.13,24.13) (24.13,-24.13)
  round 2.44 hole 2.44 unplated: (-19.05,24.13) (24.13,-19.05)
WSON_8
  rect 0.65x0.5 smd: 1(-3.775,1.905) 2(-3.775,0.635) 3(-3.775,-0.635) 4(-3.775,-1.905) 5(3.775,-1.905) 6(3.775,-0.635) 7(3.775,0.635) 8(3.775,1.905)
  rect 5.9x4.9 smd: 9(0,0)

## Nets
0V85: C933.1 C935.1 C937.1 C939.1 C1063.1 C1064.1 C1122.2 C1123.2 C1124.1 C1125.2 C1131.2 C1132.2 C1133.2 C1134.2 C1135.2 C1143.2 C1144.2 C1146.2 C1147.1 C1148.2 C1150.2 C1154.2 C1155.2 C1156.2 C1157.2 C1158.2 C1159.2 C1166.2 C1169.2 C1170.2 C1171.2 C1172.2 C1173.2 C1174.2 C1175.2 C1176.2 C1182.2 C1290.2 C1291.2 C1292.1 C1295.2 C1296.2 C1297.2 C1298.1 C1299.2 C1303.2 C1304.2 C1305.2 C1306.2 C1311.2 C1312.2 C1313.2 C1322.2 C1323.2 C1324.2 C1325.2 C1326.2 C1327.2 C1330.2 C1337.2 C1338.2 C1339.2 C1340.2 C1341.2 C1342.2 C1343.2 C1344.2 C1350.2 FB56.2 FB57.2 FB64.2 FB65.2 L17.2 R738.2 U101.J6(VDD#J6) U101.J8(VDD#J8) U101.J10(VDD#J10) U101.J12(VDD#J12) U101.K5(VDD#K5) U101.K7(VDD#K7) U101.K9(VDD#K9) U101.K11(VDD#K11) U101.K13(VDD#K13) U101.L6(VDD#L6) U101.L8(VDD#L8) U101.L10(VDD#L10) U101.L12(VDD#L12) U101.M7(VDD#M7) U101.M9(VDD#M9) U101.M11(VDD#M11) U101.M13(VDD#M13) U101.N6(VDD#N6) U101.N8(VDD#N8) U101.N10(VDD#N10) U101.N12(VDD#N12) U101.P5(VDD#P5) U101.P7(VDD#P7) U101.P9(VDD#P9) U101.P11(VDD#P11) U101.P13(VDD#P13) U101.R8(VDD#R8) U101.R10(VDD#R10) U101.R12(VDD#R12) U108.J6(VDD#J6) U108.J8(VDD#J8) U108.J10(VDD#J10) U108.J12(VDD#J12) U108.K5(VDD#K5) U108.K7(VDD#K7) U108.K9(VDD#K9) U108.K11(VDD#K11) U108.K13(VDD#K13) U108.L6(VDD#L6) U108.L8(VDD#L8) U108.L10(VDD#L10) U108.L12(VDD#L12) U108.M7(VDD#M7) U108.M9(VDD#M9) U108.M11(VDD#M11) U108.M13(VDD#M13) U108.N6(VDD#N6) U108.N8(VDD#N8) U108.N10(VDD#N10) U108.N12(VDD#N12) U108.P5(VDD#P5) U108.P7(VDD#P7) U108.P9(VDD#P9) U108.P11(VDD#P11) U108.P13(VDD#P13) U108.R8(VDD#R8) U108.R10(VDD#R10) U108.R12(VDD#R12)
0V85_XGT1_AFE: C1191.1 C1192.1 FB57.1 U101.E10(AFE_DVDD)
0V85_XGT1_VDDSRDS: C1160.1 C1161.1 C1162.1 C1163.1 C1164.1 C1165.1 C1167.1 C1168.1 FB56.1 U101.R5(VDD_SRDS#R5) U101.T8(VDD_SRDS#T8) U101.T10(VDD_SRDS#T10) U101.T12(VDD_SRDS#T12)
0V85_XGT2_AFE: C1359.1 C1360.1 FB65.1 U108.E10(AFE_DVDD)
0V85_XGT2_VDDSRDS: C1328.1 C1329.1 C1331.1 C1332.1 C1333.1 C1334.1 C1335.1 C1336.1 FB64.1 U108.R5(VDD_SRDS#R5) U108.T8(VDD_SRDS#T8) U108.T10(VDD_SRDS#T10) U108.T12(VDD_SRDS#T12)
1V0_FA_VL: C222.1 J11.1 R179.2 U1.G18(FA_VL)
1V0_USB_SVDD: C138.1 C147.1 C148.1 C149.1 C1262.1 FB11.1 U1.K9(USB_SVDD1) U1.K10(USB_SVDD2)
1V0S: C1013.2 C1017.1 C1079.1 R806.2 U95.7(OUT#7) U95.8(OUT#8)
1V2: C1114.1 C1126.1 C1127.1 C1128.1 C1129.1 C1130.1 C1145.1 C1149.1 C1236.1 C1239.1 C1240.1 C1241.1 C1248.1 C1249.1 C1293.1 C1300.1 C1301.1 C1302.1 C1308.1 C1309.1 C1310.1 L24.2 R133.1 R134.1 R887.1 R895.1 R930.2 R960.1 R968.1 U1.T6(TVDD) U101.D4(VA12#D4) U101.D6(VA12#D6) U101.E5(VA12#E5) U101.E7(VA12#E7) U101.E9(VA12#E9) U108.D4(VA12#D4) U108.D6(VA12#D6) U108.E5(VA12#E5) U108.E7(VA12#E7) U108.E9(VA12#E9)
1V5: C609.1 C610.1 C611.1 C612.1 C613.1 C614.1 C959.1 C960.1 C961.1 C964.1 C1095.1 C1096.1 J19.6(1.5V#6) J19.28(1.5V#28) J19.48(1.5V#48) J20.6(1.5V#6) J20.28(1.5V#28) J20.48(1.5V#48) L19.2 R753.2
1V05_EC1_AVDD: C343.1 C344.1 C353.1 C354.1 C355.1 L4.2 R826.2 U49.3(AVDD10#3) U49.9(AVDD10#9) U49.40(AVDD10#40)
1V05_EC1_DVDD: C348.1 C349.1 R826.1 U49.28(DVDD10#28) U49.36(DVDD10#36)
1V05_EC2_AVDD: C312.1 C313.1 C321.1 C322.1 C323.1 L3.2 R824.2 U46.3(AVDD10#3) U46.9(AVDD10#9) U46.40(AVDD10#40)
1V05_EC2_DVDD: C316.1 C317.1 R824.1 U46.28(DVDD10#28) U46.36(DVDD10#36)
1V8: C23.1 C24.1 C25.1 C26.1 C30.1 C31.1 C32.1 C35.1 C50.1 C53.1 C195.1 C196.1 C197.1 C198.1 C199.1 C232.1 C729.1 C730.1 C1011.1 C1012.1 C1274.1 C1275.1 C1276.1 C1277.1 FB13.2 FB50.1 J53.3 Q11.1 Q11.2 Q11.3 Q44.2(S) R5.2 R6.2 R7.2 R9.2 R10.2 R11.2 R41.2 R42.2 R43.2 R44.2 R47.2 R82.2 R102.2 R188.1 R195.1 R502.1 R504.1 R506.1 R508.1 R656.2 R797.1 R798.1 R799.1 R800.1 R801.2 R802.2 R803.2 R804.2 R864.1 R939.1 R952.2 R953.2 U1.G9(TH_VDD) U1.J14(OVDD1) U1.J15(OVDD2) U1.J16(OVDD3) U1.J17(OVDD4) U1.J18(OVDD5) U1.J19(OVDD6) U2.7(VCC#7) U2.18(VCC#18) U2.31(VCC#31) U2.42(VCC#42) U4.29(VIO) U8.5(VCC) U9.5(VCC) U10.5(VCC) U20.13(VCCB) U22.1(VCC1) U107.D3(VCC#D3) U107.G4(VCC#G4) U107.H8(VCC#H8) U107.J6(VCC#J6)
1V8_0641_VDD: C1049.1 C1050.1 C1051.1 FB55.2 R839.1 R841.1 U97.16(VDD1.8#16) U97.31(VDD1.8#31)
1V8_0641_VDDA: C736.1 C737.1 R841.2 U97.26(VDDA1.8)
1V8_0641_VDDIO: C1044.1 C1045.1 C1046.1 C1047.1 C1048.1 C1052.1 FB54.1 U97.5(VDDREF1.8) U97.12(VDDIO#12) U97.17(VDDIO#17) U97.27(VDDIO#27) U97.32(VDDIO#32) U97.39(VDDIO#39)
1V8_0641_VDDXTAL: C1040.1 C1041.1 R839.2 U97.4(VDDXTAL1.8)
1V8_MTR: C208.1 J10.1 R178.2 U1.F11(PROG_MTR)
1V8_OSC_USB: C135.1 C136.1 FB10.2 X1.4(VDD)
1V8_SFP: C192.1 J9.1 R177.2 U1.F12(PROG_SFP)
1V8_SLP: C52.1 C133.1 C134.1 C209.1 C210.1 C211.1 C220.1 C698.1 C699.1 C700.1 C711.1 C712.1 C713.1 C714.1 C715.1 C716.1 C720.1 C721.1 C735.1 C958.1 C962.1 C963.1 C965.1 C1015.1 C1097.1 C1098.1 C1101.1 C1104.1 C1105.1 FB10.1 FB48.1 FB54.2 FB55.1 J9.2 J10.2 L20.2 Q11.5 R69.2 R70.2 R81.2 R83.2 R84.2 R85.2 R94.1 R96.1 R98.1 R101.2 R194.1 R757.2 R813.2 R829.1 R834.1 R843.1 R844.1 R876.2 R877.2 R878.2 R879.2 U1.J11(O1VDD1) U1.J12(O1VDD2) U1.J13(O1VDD3) U21.1(VCC1) U65.A3(VCCIO2#A3) U65.A14(VCCIO2#A14) U65.C16(VCCIO2#C16) U65.F8(VCCIO2#F8) U65.F9(VCCIO2#F9) U65.H8(VCCINT#H8) U65.H10(VCCINT#H10) U65.H11(VCCIO2#H11) U65.J7(VCCINT#J7) U65.J9(VCCINT#J9) U65.J11(VCCIO2#J11) U65.P16(VCCIO2#P16) U95.1(IN#1) U95.2(IN#2) U97.11(VDDDIG1.8)
1V8_USB_OVDD: C170.1 C171.1 C172.1 C173.1 C174.1 FB13.1 U1.J9(USB_OVDD1) U1.J10(USB_OVDD2)
1V8_XGT1_VREGSRDS: C1177.1 C1178.1 C1179.1 C1180.1 U101.T4(P0_VREG_SRDS#T4) U101.T6(P0_VREG_SRDS#T6)
1V8_XGT2_VREGSRDS: C1345.1 C1346.1 C1347.1 C1348.1 U108.T4(P0_VREG_SRDS#T4) U108.T6(P0_VREG_SRDS#T6)
1V35: C137.1 C139.1 C140.1 C141.1 C142.1 C143.1 C144.1 C145.1 C146.1 C150.1 C151.1 C152.1 C153.1 C154.1 C155.1 C156.1 C157.1 C163.1 C164.1 C165.1 C166.1 C167.1 C168.1 C169.1 C1014.1 C1254.1 C1255.1 C1256.1 C1257.1 C1258.1 C1259.1 C1260.1 C1261.1 Q31.1 Q31.2 Q31.3 R1.1 R4.1 R189.2 R192.2 R782.2 U1.AA27(G1VDD17) U1.AD27(G1VDD18) U1.AF27(G1VDD19) U1.D27(G1VDD01) U1.F27(G1VDD02) U1.H27(G1VDD03) U1.K21(G1VDD04) U1.K27(G1VDD05) U1.L21(G1VDD06) U1.M21(G1VDD07) U1.M27(G1VDD08) U1.N21(G1VDD09) U1.P21(G1VDD10) U1.P27(G1VDD11) U1.R21(G1VDD12) U1.T21(G1VDD13) U1.U21(G1VDD14) U1.U27(G1VDD15) U1.W27(G1VDD16)
1V35_SLP: C1.1 C2.1 C3.1 C4.1 C5.1 C6.1 C7.1 C8.1 C9.1 C10.1 C11.1 C12.1 C13.1 C14.1 C880.1 C881.1 C934.1 C936.1 C940.1 C941.1 C998.1 C999.1 C1069.1 C1070.1 C1254.2 C1255.2 C1256.2 C1257.2 C1258.2 C1259.2 C1260.2 C1261.2 J1.51(VDD#51) J1.54(VDD#54) J1.57(VDD#57) J1.60(VDD#60) J1.62(VDD#62) J1.65(VDD#65) J1.66(VDD#66) J1.69(VDD#69) J1.72(VDD#72) J1.75(VDD#75) J1.78(VDD#78) J1.170(VDD#170) J1.173(VDD#173) J1.176(VDD#176) J1.179(VDD#179) J1.182(VDD#182) J1.183(VDD#183) J1.186(VDD#186) J1.189(VDD#189) J1.191(VDD#191) J1.194(VDD#194) J1.197(VDD#197) L18.2 Q31.5 R2.1 R695.2 R736.2 U81.2(VLDOIN)
2V1: C1136.1 C1137.1 C1138.1 C1139.1 C1140.1 C1141.1 C1142.1 C1151.1 C1152.1 C1153.1 C1237.1 C1238.1 C1242.1 C1243.1 C1252.1 C1253.1 C1294.1 C1307.1 C1314.1 C1315.1 C1316.1 C1317.1 C1318.1 C1319.1 C1320.1 C1321.1 FB58.2 FB66.2 FB68.2 FB69.2 L25.2 R929.2 U101.A3(VA22#A3) U101.A5(VA22#A5) U101.A7(VA22#A7) U101.A9(VA22#A9) U101.C3(VA22#C3) U101.C5(VA22#C5) U101.C7(VA22#C7) U101.C9(VA22#C9) U108.A3(VA22#A3) U108.A5(VA22#A5) U108.A7(VA22#A7) U108.A9(VA22#A9) U108.C3(VA22#C3) U108.C5(VA22#C5) U108.C7(VA22#C7) U108.C9(VA22#C9)
2V1_XGT1_VDDSRDS: C1181.1 C1183.1 C1184.1 C1185.1 FB68.1 U101.P4(V22_SRDS#P4) U101.R3(V22_SRDS#R3)
2V1_XGT1_XTAL: C1193.1 C1194.1 FB58.1 U101.E18(VA22_XTAL)
2V1_XGT2_VDDSRDS: C1349.1 C1351.1 C1352.1 C1353.1 FB69.1 U108.P4(V22_SRDS#P4) U108.R3(V22_SRDS#R3)
2V1_XGT2_XTAL: C1361.1 C1362.1 FB66.1 U108.E18(VA22_XTAL)
2V5: C175.1 C176.1 C177.1 C314.1 C315.1 C1121.1 C1186.2 C1187.2 C1188.2 C1189.2 C1190.2 C1289.1 C1354.2 C1355.2 C1356.2 C1357.2 C1358.2 FB59.2 FB67.2 J51.6 J55.6 Q17.1 Q17.2 Q17.3 R138.2 R229.2 R230.2 R231.2 R232.2 R672.2 R884.2 R886.1 R897.2 R941.2 R942.2 R943.2 R957.2 R958.1 R965.2 R966.2 R970.2 R976.2 U1.V8(LVDD1) U1.W8(LVDD2) U46.15(DVDD33#15) U46.21(DVDD33#21) U101.E3(VDD_FLASH) U101.J3(VDD_IO#J3) U101.K4(VDD_IO#K4) U101.K16(VDD_IO#K16) U101.L16(VDD_IO#L16) U102.3(W\P\) U102.7(H\O\L\D\) U102.8(VCC) U108.E3(VDD_FLASH) U108.J3(VDD_IO#J3) U108.K4(VDD_IO#K4) U108.K16(VDD_IO#K16) U108.L16(VDD_IO#L16) U109.3(W\P\) U109.7(H\O\L\D\) U109.8(VCC)
2V5_SLP: C57.1 C58.1 C178.1 C179.1 C180.1 C346.1 C347.1 C982.1 C983.1 C984.1 C988.1 C1099.1 C1100.1 L21.2 Q17.5 R71.2 R72.2 R131.1 R132.1 R258.2 R259.2 R260.2 R774.2 R875.1 R881.1 U1.T8(L1VDD1) U1.U8(L1VDD2) U23.5(VCC) U24.5(VCC) U49.15(DVDD33#15) U49.21(DVDD33#21)
3V3: C33.1 C34.1 C36.1 C37.1 C48.1 C49.1 C51.1 C92.1 C93.1 C94.1 C181.1 C182.1 C183.1 C184.1 C272.1 C286.1 C293.1 C319.1 C320.1 C324.1 C325.1 C326.1 C600.1 C601.1 C602.1 C603.1 C604.1 C605.1 C626.1 C627.1 C628.1 C629.1 C742.1 C743.1 C1028.1 C1081.1 C1375.1 C1376.1 C1377.1 FB12.2 FB26.1 FB52.1 FB70.1 FB71.1 J18.A9(+3V3#A9) J18.A10(+3V3#A10) J18.B8(+3V3#B8) J18.B10(+3V3AUX) J19.2(3.3V#2) J19.24(3.3VAUX) J19.52(3.3V#52) J20.2(3.3V#2) J20.24(3.3VAUX) J20.52(3.3V#52) J43.10 J43.12 J43.14 J43.16 J53.1 Q1.1(G) Q2.1(G) Q18.1 Q18.2 Q18.3 Q45.2(S) Q50.2(E) R54.2 R55.2 R56.2 R57.2 R65.2 R66.2 R73.2 R74.2 R86.2 R87.2 R88.2 R89.2 R95.2 R97.2 R99.1 R107.1 R108.2 R109.2 R110.1 R111.1 R112.1 R113.1 R114.1 R155.2 R156.2 R158.2 R159.2 R234.2 R235.2 R398.2 R399.2 R402.2 R403.2 R404.2 R405.2 R406.2 R407.2 R408.2 R409.2 R410.2 R411.2 R549.1 R673.2 R822.1 R823.1 R849.1 R850.1 R851.1 R852.1 R871.2 R872.2 R988.1 R989.1 R990.1 R991.1 R992.1 R994.1 R996.1 R998.1 U1.M8(CVDD) U1.N8(DVDD1) U1.P8(DVDD2) U1.R8(DVDD3) U4.43(VCC) U13.2(VCC) U15.8(VCC) U19.1(A0) U19.2(A1) U19.13(A2) U19.16(VDD) U20.16(VCCA) U22.5(VCC) U39.16(VCC) U41.16(VCC) U44.8(VCC) U46.6(AVDD33#6) U46.37(DVDD33#37) U46.41(AVDD33#41) U46.44(VDDREG#44) U46.45(VDDREG#45) U68.10(VCC#10) U68.16(VCC#16) U110.1(VDD#1) U110.6(VDD#6) U110.10(VDD#10)
3V3_859S0212I_1: C1390.1 C1391.1 FB70.2 U113.9(VCC_TAP) U113.16(VCC)
3V3_859S0212I_2: C1392.1 C1393.1 FB71.2 U112.9(VCC_TAP) U112.16(VCC)
3V3_OSC_CPLD: C703.1 C704.1 FB47.2 R494.1 X2.4(VDD)
3V3_PGOOD: R771.2 U65.K1(IO_B1_K1) U90.3(PGOOD)
3V3_SLP: C20.1 C54.1 C295.1 C350.1 C351.1 C356.1 C357.1 C358.1 C701.1 C702.1 C705.1 C706.1 C707.1 C708.1 C709.1 C710.1 C882.1 C985.1 C986.1 C987.1 C989.1 C1002.1 C1016.1 C1066.1 C1067.1 C1068.1 C1102.1 C1103.1 C1115.1 C1223.1 C1379.1 D43.2 D44.2 FB29.1 FB47.1 J1.117(SA0) J1.236(VDDSPD) J26.4 L22.2 Q18.5 R90.2 R91.2 R204.2 R252.1 R263.2 R264.2 R497.1 R498.1 R697.2 R703.2 R704.2 R705.2 R771.1 R772.2 R825.1 R853.2 R940.2 R1016.2 U21.5(VCC) U45.1(VDD) U49.6(AVDD33#6) U49.37(DVDD33#37) U49.41(AVDD33#41) U49.44(VDDREG#44) U49.45(VDDREG#45) U65.C1(VCCIO1#C1) U65.H6(VCCIO1#H6) U65.J6(VCCIO1#J6) U65.L8(VCCIO1#L8) U65.L9(VCCIO1#L9) U65.P1(VCCIO1#P1) U65.T3(VCCIO1#T3) U65.T14(VCCIO1#T14) U81.10(VIN) U83.4(VCC) U95.4(BIAS) U100.8(VCC) U104.5(VCC) U111.6(VS)
3V3_USB_HVDD: C158.1 C159.1 C160.1 C161.1 C162.1 FB12.1 U1.J8(USB_HVDD1) U1.K8(USB_HVDD2)
3V3A_843002: C750.1 C751.1 R549.2 U68.8(VCCA)
3V3O_843002: C746.1 C747.1 FB52.2 U68.2(VCCO#2) U68.20(VCCO#20)
5V0_SB: C897.1 C898.1 J37.9(+5VSB) R710.2 R711.2 R715.1 U84.7(P\R\E\) U84.8(VCC) U85.5(VCC)
5V0_SLP: C130.1 C131.1 C925.1 C926.1 C928.2 C929.2 C930.1 C931.1 C950.2 C951.2 C952.1 C953.1 C954.1 C955.1 C973.2 C974.2 C975.1 C976.1 C979.1 C980.1 C1053.2 C1054.2 C1055.2 C1056.2 C1057.2 C1058.2 C1112.1 C1113.1 C1208.1 C1209.1 C1210.1 C1211.1 C1213.1 C1226.2 C1227.2 C1228.1 C1229.1 C1230.2 C1232.2 C1233.1 C1234.1 J37.4(+5VDC#4) J37.6(+5VDC#6) J37.19(+5VDC#19) J37.20(+5VDC#20) R706.2 R728.1 R730.1 R732.1 R734.1 R737.1 R739.1 R746.1 R747.1 R750.1 R752.1 R754.1 R756.1 R764.1 R765.1 R768.1 R770.1 R773.1 R904.1 R906.1 R908.1 R921.1 R923.1 R925.1 R927.1 R931.1 R932.1 U37.1(INA) U37.5(INB) U38.5 U86.10(VCC) U86.13(VIN) U87.10(VCC) U87.13(VIN) U88.10(VCC) U88.13(VIN) U89.10(VCC) U89.13(VIN) U90.10(VCC) U90.13(VIN) U91.10(VCC) U91.13(VIN) U103.10(VCC) U103.13(VIN) U105.10(VCC) U105.13(VIN) U106.10(VCC) U106.13(VIN)
5V0_USB1: C127.1 C128.1 C129.1 D4.1 FB6.2 R164.2 U37.10(OUTA)
5V0_USB2: C124.1 C125.1 C126.1 D3.1 FB8.2 R163.2 U37.6(OUTB)
12V: C84.1 C85.1 C620.1 C621.1 C622.1 C623.1 C624.1 C625.1 C1080.1 F9.1 F11.1 F12.1 F13.1 F14.1 F15.1 J18.A2(+12V#A2) J18.A3(+12V#A3) J18.B1(+12V#B1) J18.B2(+12V#B2) J18.B3(+12V#B3) J43.2 J43.4 J43.6 Q12.5 Q12.6 Q12.7 Q12.8 R700.1 R861.1 R862.1 R863.1 R870.2 R986.1 R987.1
12V_SLP: C874.1 C1278.1 C1279.1 C1280.1 C1281.1 F10.1 J37.10(+12VDC) Q12.1 Q12.2 Q12.3 R662.1 R663.1 R678.1 R679.1 R701.1 R784.1 R818.1 R819.2 R916.2 R947.1
-5VDC: J37.18(-5VDC)
-12VDC: J37.12(-12VDC)
AGND_SD1_PLL1: C259.2 C260.2 C261.2 R190.1 U1.AA16(SD_GND07)
AGND_SD1_PLL2: C264.2 C265.2 C266.2 R193.1 U1.AA20(SD_GND10)
AVDD_CGA1: C257.1 C258.1 R188.2 U1.G11(AVDD_CGA1)
AVDD_CGA2: C1263.1 C1264.1 R939.2 U1.G12(NC_G12)
AVDD_DDR1: C269.1 C270.1 R195.2 U1.E20(AVDD_D1)
AVDD_PLAT: C267.1 C268.1 R194.2 U1.G10(AVDD_PLAT)
AVDD_SD1_PLL1: C259.1 C260.1 C261.1 R189.1 U1.AB16(AVDD_SD1_PLL1)
AVDD_SD1_PLL2: C264.1 C265.1 C266.1 R192.1 U1.AB20(AVDD_SD1_PLL2)
